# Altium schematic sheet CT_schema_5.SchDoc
size 278 x 170 mm
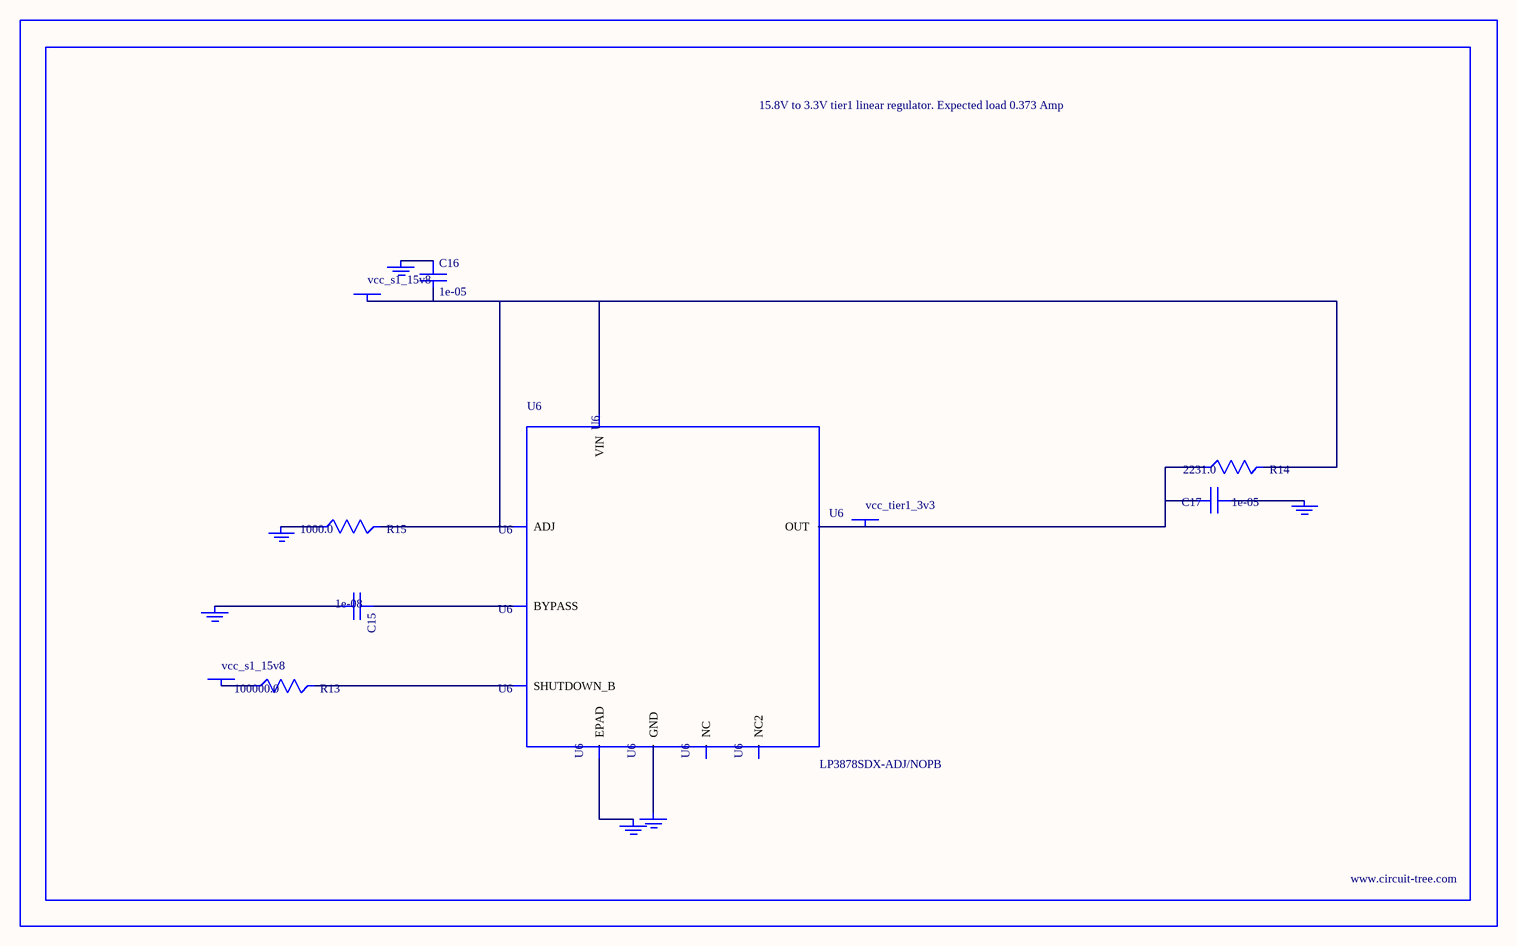
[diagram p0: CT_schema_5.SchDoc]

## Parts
BORDER4  (no value)
C15  1e-08  [C0402]
C16  1e-05  [C1210]
C17  1e-05  [C1210]
GND_INSTANCE_4_0  (no value)
GND_INSTANCE_4_1  (no value)
GND_INSTANCE_4_2  (no value)
GND_INSTANCE_4_3  (no value)
GND_INSTANCE_4_4  (no value)
GND_INSTANCE_4_5  (no value)
POWER_INSTANCE_4_0  vcc_s1_15v8
POWER_INSTANCE_4_1  vcc_s1_15v8
POWER_INSTANCE_4_2  vcc_tier1_3v3
R13  100000.0  [R0603]
R14  2231.0  [R0603]
R15  1000.0  [R0603]
U6  LP3878SDX-ADJ/NOPB  [WSON-8]

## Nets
NetC15_1: C15.1 U6.1(BYPASS)
NetC15_2: C15.2 GND_INSTANCE_4_0.0(GND)
NetC16_1: C16.1 GND_INSTANCE_4_1.0(GND)
NetC16_2: C16.2 POWER_INSTANCE_4_0.0(PWR) R14.2 R15.2 U6.4(VIN) U6.6(ADJ)
NetC17_1: C17.1 GND_INSTANCE_4_2.0(GND)
NetC17_2: C17.2 POWER_INSTANCE_4_2.0(PWR) R14.1 U6.5(OUT)
NetGND_INSTANCE_4_3_0: GND_INSTANCE_4_3.0(GND) R15.1
NetGND_INSTANCE_4_4_0: GND_INSTANCE_4_4.0(GND) U6.PAD(EPAD)
NetGND_INSTANCE_4_5_0: GND_INSTANCE_4_5.0(GND) U6.3(GND)
NetPOWER_INSTANCE_4_1_0: POWER_INSTANCE_4_1.0(PWR) R13.1
NetR13_2: R13.2 U6.8(SHUTDOWN_B)

Not connected (* = marked no-connect by the designer): U6 2(NC) 7(NC2)

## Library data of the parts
BORDER4 = BORDER_PAGE4
C15 = C0402C103K3RAC
C16 = C1210C106K5PACTU
C17 = GRM32DR61E106MA12L
GND_INSTANCE_4_0-GND_INSTANCE_4_5 = GND
POWER_INSTANCE_4_0-POWER_INSTANCE_4_2 = PWR
R13 = RC0603JR-07100KL
R14 = R14
R15 = RC0603JR-071KL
